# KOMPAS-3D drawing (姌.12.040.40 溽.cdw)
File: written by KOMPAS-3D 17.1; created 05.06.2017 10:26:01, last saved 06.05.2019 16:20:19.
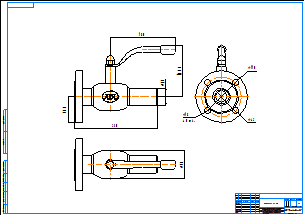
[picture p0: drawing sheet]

Sheet 1: A1, landscape

Title block, sheet 1: name: КШ.12.040.40 фс; material: Внимание! Данный продукт является объектом авторского права ООО «Торговый Дом АДЛ». / Запрещается изменение, копирование, распространение / (в том числе путем копирования на другие сайты и ресурсы в Интернете) / или любое иное использование информации и объектов без предварительного / согласия правообладателя (ООО «Торговый Дом АДЛ»).; sheets: 1; organisation: ООО "Торговый дом АДЛ"; sheet format: A1; stored path: C:\Users\kka\KOMPAS_Work\Модели кранов для исследований\Все краники\Редуцированный резьба-сварка ШК БИВАЛ\КШ.02.015.40 рс.cdw

Views: Вид 1, Проекционный вид 2, Проекционный вид 3
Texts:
  Klimkovich
  ADL
Dimensions and other numbers on the sheet: 180; 48; 230; 142,6; 110; 72,5; 42; 18; 4 Отв.; 76; 1:1; 1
